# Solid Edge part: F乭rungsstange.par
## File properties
Username: bmolnar
Dokumentum tartalom típus: 0
Author: bmolnar
Last saved by: bmolnar
Revision: 82
Sűrűség: 0,000 kg/m^3
Pontosság: 0,990
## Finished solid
Body 1: solid body, 8 faces, 7 edges, 4 vertices.
  Faces by surface: cone 4, cylinder 2, plane 2
  Edges by curve: circle 7
Bounding box of the edges (mm): 5.000 x 5.000 x 83.000, from (-2.5, -2.5, -59) to (2.5, 2.5, 24).
Cylindrical faces by radius (mm): R1.2295 x1, R2.5 x1
Conical faces (half-angle, radius in mm at the cone's reference point): 45 deg R1.3295 x1, 45 deg R2.25 x1, 45 deg R2.5 x1, 59 deg R0.6148 x1
Planar faces by outward normal: +z 1, -z 1
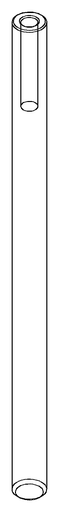
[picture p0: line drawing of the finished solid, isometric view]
